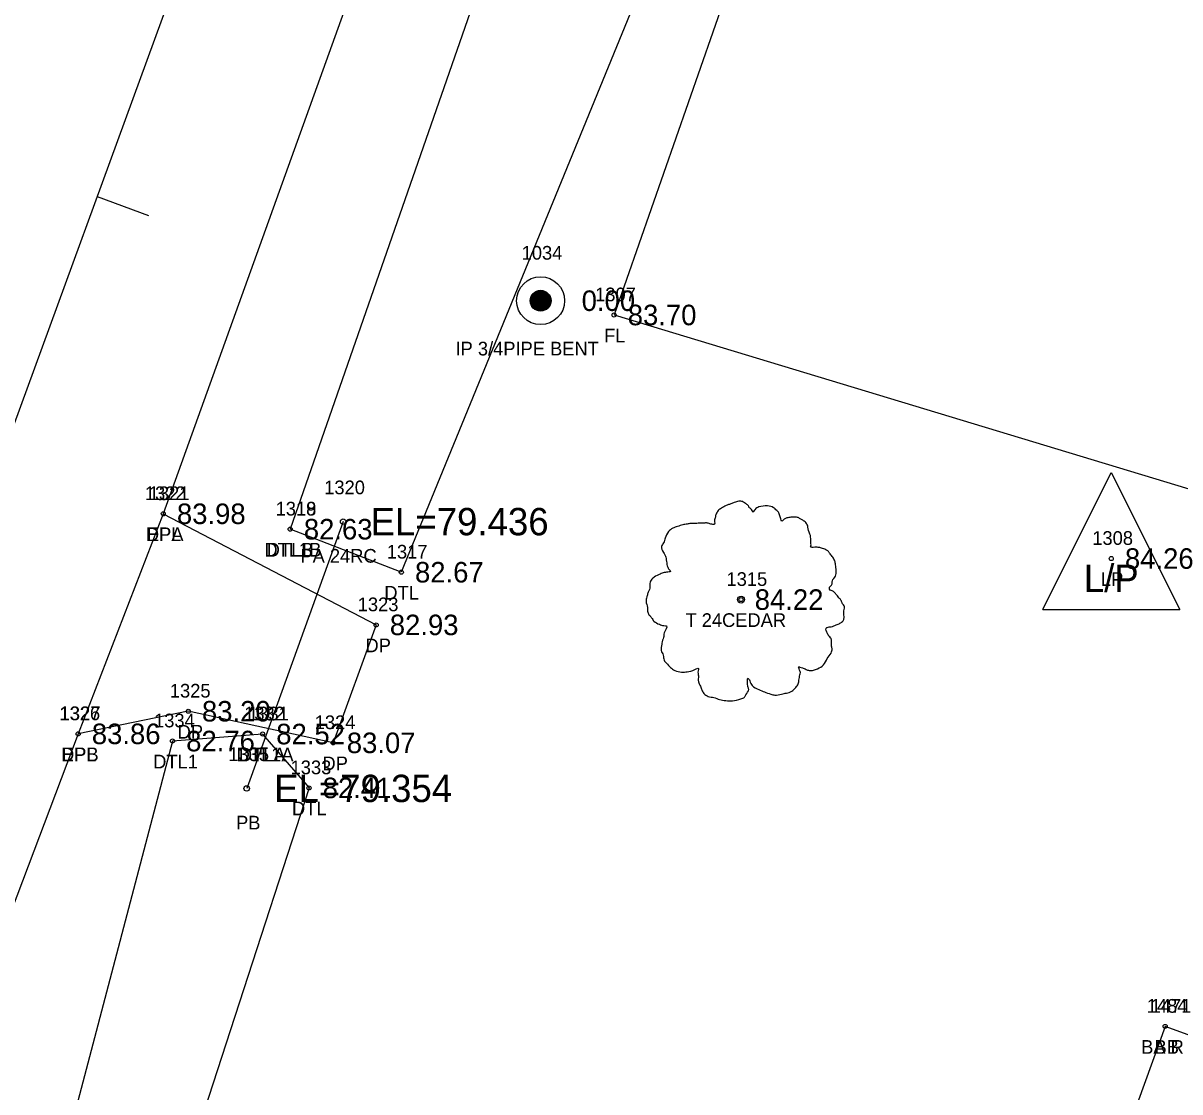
# Model space of a CAD drawing. Extents: x 2139392 to 2143384, y 505395 to 510520.
# Drawn here: x 2141229.8 to 2141314.3, y 509747.3 to 509825.4 of the extents above; entities that cross this region are included whole.
import ezdxf

# ---------------------------------------------------------------- set-up
doc = ezdxf.new("R2010")
doc.units = 0
for name, color, linetype in [('RD_EX_Bldg', 7, 'Continuous'), ('RD_EX_Bldg_txCode', 7, 'Continuous'), ('RD_EX_DR_Pipe', 7, 'Continuous'), ('RD_EX_DR_Pipe_txCode', 7, 'Continuous'), ('RD_EX_Driveway', 7, 'Continuous'), ('RD_EX_Driveway_txCode', 7, 'Continuous'), ('RD_EX_DV_Prop_txCode', 7, 'Continuous'), ('RD_EX_DV_PropPin', 7, 'Continuous'), ('RD_EX_Fence_Other', 7, 'Continuous'), ('RD_EX_Fence_Other_txCode', 7, 'Continuous'), ('RD_EX_H2O', 7, 'Continuous'), ('RD_EX_H2O_txCode', 7, 'Continuous'), ('RD_EX_Road', 7, 'Continuous'), ('RD_EX_Road_txCode', 7, 'Continuous'), ('RD_EX_TX_Driveway_ELEV', 7, 'Continuous'), ('RD_EX_TX_DV_Prop_ELEV', 7, 'Continuous'), ('RD_EX_TX_Fence_Other_ELEV', 7, 'Continuous'), ('RD_EX_TX_H2O_ELEV', 7, 'Continuous'), ('RD_EX_TX_Road_ELEV', 7, 'Continuous'), ('RD_EX_TX_UT_ELEV', 7, 'Continuous'), ('RD_EX_TX_VEG_ELEV', 7, 'Continuous'), ('RD_EX_UT', 7, 'Continuous'), ('RD_EX_UT_txCode', 7, 'Continuous'), ('RD_EX_VEG', 7, 'Continuous'), ('RD_EX_VEG_txCode', 7, 'Continuous'), ('RD_HC_Cl', 7, 'Continuous'), ('RD_HC_Data_Tic', 7, 'Continuous'), ('RD_SMD_Locator', 7, 'Continuous'), ('RD_TX_Pipe_ElevEX', 7, 'Continuous')]:
    doc.layers.add(name, color=color, linetype=linetype)

msp = doc.modelspace()

# ---------------------------------------------------------------- linework, layer by layer
at = {"layer": 'RD_EX_Bldg'}
msp.add_lwpolyline([(2141313.226, 509752.054), (2141304.219, 509727.145), (2141295.277, 509730.38), (2141286.846, 509707.265), (2141295.758, 509703.984), (2141281.839, 509665.488), (2141306.214, 509656.42), (2141337.675, 509743.19), (2141313.226, 509752.054)], dxfattribs=at)
at = {"layer": 'RD_EX_DR_Pipe'}
msp.add_line((2141253.154, 509788.94), (2141246.105, 509769.444), dxfattribs=at)
at = {"layer": 'RD_EX_Driveway'}
msp.add_lwpolyline([(2141240.004, 509789.512), (2141255.562, 509781.393), (2141252.42, 509772.775), (2141241.833, 509775.084), (2141233.785, 509773.43)], dxfattribs=at)
at = {"layer": 'RD_EX_DV_PropPin'}
for p, q in [((2141266.987, 509804.608), (2141266.987, 509805.556)), ((2141267.022, 509804.567), (2141267.022, 509805.597)), ((2141267.057, 509804.531), (2141267.057, 509805.633)), ((2141267.092, 509804.5), (2141267.092, 509805.664)), ((2141267.127, 509804.472), (2141267.127, 509805.692)), ((2141267.162, 509804.447), (2141267.162, 509805.717)), ((2141267.197, 509804.426), (2141267.197, 509805.738)), ((2141267.232, 509804.406), (2141267.232, 509805.758)), ((2141267.267, 509804.389), (2141267.267, 509805.775)), ((2141267.302, 509804.374), (2141267.302, 509805.79)), ((2141267.337, 509804.362), (2141267.337, 509805.802)), ((2141267.372, 509804.351), (2141267.372, 509805.813)), ((2141267.407, 509804.341), (2141267.407, 509805.823)), ((2141267.442, 509804.334), (2141267.442, 509805.83)), ((2141267.477, 509804.328), (2141267.477, 509805.836)), ((2141267.512, 509804.324), (2141267.512, 509805.84)), ((2141267.547, 509804.322), (2141267.547, 509805.842)), ((2141267.582, 509804.321), (2141267.582, 509805.843)), ((2141267.617, 509804.322), (2141267.617, 509805.842)), ((2141267.652, 509804.324), (2141267.652, 509805.84)), ((2141267.687, 509804.328), (2141267.687, 509805.836)), ((2141267.722, 509804.334), (2141267.722, 509805.83)), ((2141267.757, 509804.341), (2141267.757, 509805.823)), ((2141267.792, 509804.351), (2141267.792, 509805.813)), ((2141267.827, 509804.362), (2141267.827, 509805.802)), ((2141267.862, 509804.374), (2141267.862, 509805.79)), ((2141267.897, 509804.389), (2141267.897, 509805.775)), ((2141267.932, 509804.406), (2141267.932, 509805.758)), ((2141267.967, 509804.426), (2141267.967, 509805.738)), ((2141268.002, 509804.447), (2141268.002, 509805.717)), ((2141268.037, 509804.472), (2141268.037, 509805.692)), ((2141268.072, 509804.5), (2141268.072, 509805.664)), ((2141268.107, 509804.531), (2141268.107, 509805.633)), ((2141268.142, 509804.567), (2141268.142, 509805.597)), ((2141268.177, 509804.608), (2141268.177, 509805.556)), ((2141266.846, 509804.886), (2141266.846, 509805.278)), ((2141266.881, 509804.784), (2141266.881, 509805.38)), ((2141266.917, 509804.712), (2141266.917, 509805.452)), ((2141266.952, 509804.655), (2141266.952, 509805.509)), ((2141268.212, 509804.655), (2141268.212, 509805.509)), ((2141268.247, 509804.712), (2141268.247, 509805.452)), ((2141268.282, 509804.784), (2141268.282, 509805.38)), ((2141268.317, 509804.886), (2141268.317, 509805.278))]:
    msp.add_line(p, q, dxfattribs=at)
for radius in [1.75, 0.761]:
    msp.add_circle((2141267.582, 509805.082), radius, dxfattribs=at)
at = {"layer": 'RD_EX_Fence_Other'}
msp.add_lwpolyline([(2141429.607, 510048.099), (2141379.492, 510067.668), (2141363.998, 510064.859), (2141272.951, 509804.039), (2141395.498, 509766.949)], dxfattribs=at)
at = {"layer": 'RD_EX_H2O'}
for points in [[(2141358.836, 510073.731), (2141351.949, 510067.817), (2141335.192, 510023.257), (2141318.106, 509975.216), (2141278.813, 509873.195), (2141249.279, 509788.386)], [(2141358.836, 510073.731), (2141359.889, 510066.727), (2141343.927, 510018.933), (2141329.024, 509971.909), (2141291.465, 509868.396), (2141257.403, 509785.243), (2141249.279, 509788.386)], [(2141247.263, 509773.417), (2141240.68, 509772.906), (2141231.532, 509738.062), (2141231.201, 509735.666), (2141238.226, 509732.828), (2141239.805, 509736.073)], [(2141247.263, 509773.417), (2141250.657, 509769.482), (2141239.805, 509736.073)]]:
    msp.add_lwpolyline(points, dxfattribs=at)
at = {"layer": 'RD_EX_Road'}
msp.add_lwpolyline([(2141412.621, 510288.462), (2141398.288, 510238.157), (2141381.653, 510185.386), (2141379.05, 510176.508), (2141367.082, 510141.573), (2141363.583, 510131.95), (2141345.234, 510080.356), (2141326.054, 510027.028), (2141308.64, 509979.398), (2141271.244, 509876.373), (2141240.004, 509789.512), (2141233.785, 509773.43), (2141223.565, 509746.41), (2141212.184, 509714.932), (2141204.363, 509694.358), (2141197.988, 509676.557), (2141193.665, 509664.596), (2141161.614, 509577.238), (2141123.752, 509473.606), (2141115.502, 509450.651), (2141102.094, 509414.611), (2141086.274, 509371.268), (2141050.416, 509272.831)], dxfattribs=at)
at = {"layer": 'RD_EX_UT'}
for p, q in [((2141304.285, 509782.517), (2141309.285, 509792.517)), ((2141309.285, 509792.517), (2141314.285, 509782.517)), ((2141304.285, 509782.517), (2141314.285, 509782.517))]:
    msp.add_line(p, q, dxfattribs=at)
at = {"layer": 'RD_EX_VEG'}
for centre, radius in [((2141282.23, 509783.242), 0.25), ((2141282.217, 509783.223), 0.0001)]:
    msp.add_circle(centre, radius, dxfattribs=at)
for points in [[(2141282.362, 509790.409), (2141282.062, 509790.434), (2141281.737, 509790.334), (2141281.487, 509790.234), (2141281.262, 509790.159), (2141281.037, 509790.059), (2141280.738, 509789.884), (2141280.513, 509789.684), (2141280.388, 509789.434), (2141280.338, 509789.209), (2141280.288, 509788.935), (2141280.288, 509788.76), (2141280.163, 509788.735), (2141280.013, 509788.76), (2141279.763, 509788.835), (2141279.513, 509788.835), (2141279.263, 509788.835), (2141278.913, 509788.81), (2141278.563, 509788.81), (2141278.289, 509788.76), (2141277.964, 509788.71), (2141277.589, 509788.585), (2141277.239, 509788.46), (2141276.939, 509788.21), (2141276.689, 509787.735), (2141276.564, 509787.385), (2141276.414, 509787.135), (2141276.564, 509786.686), (2141276.739, 509786.336), (2141276.764, 509786.136), (2141276.839, 509785.711), (2141276.939, 509785.486), (2141277.064, 509785.286), (2141276.989, 509785.261), (2141276.614, 509785.211), (2141276.314, 509785.111), (2141275.89, 509784.886), (2141275.665, 509784.661), (2141275.565, 509784.336), (2141275.54, 509783.987), (2141275.44, 509783.787), (2141275.365, 509783.512), (2141275.34, 509783.437), (2141275.29, 509783.112), (2141275.39, 509782.662), (2141275.415, 509782.312), (2141275.54, 509782.087), (2141275.69, 509781.913), (2141275.865, 509781.663), (2141276.264, 509781.438), (2141276.589, 509781.338), (2141276.789, 509781.313), (2141276.614, 509780.813), (2141276.564, 509780.463), (2141276.439, 509780.063), (2141276.439, 509779.988), (2141276.389, 509779.514), (2141276.539, 509779.189), (2141276.614, 509778.814), (2141276.789, 509778.589), (2141277.064, 509778.289), (2141277.389, 509778.064), (2141277.889, 509777.939), (2141278.289, 509777.964), (2141278.863, 509778.139), (2141279.113, 509778.214), (2141279.088, 509778.039), (2141279.113, 509777.664), (2141279.113, 509777.24), (2141279.263, 509776.915), (2141279.363, 509776.64), (2141279.513, 509776.39), (2141279.838, 509776.165), (2141280.238, 509776.09), (2141280.663, 509775.94), (2141281.112, 509775.865), (2141281.612, 509775.84), (2141282.212, 509775.99), (2141282.487, 509776.115), (2141282.587, 509776.29), (2141282.787, 509776.665), (2141282.737, 509776.89), (2141282.762, 509777.49), (2141282.862, 509777.315), (2141283.037, 509776.965), (2141283.536, 509776.665), (2141283.936, 509776.49), (2141284.411, 509776.34), (2141284.711, 509776.265), (2141285.186, 509776.34), (2141285.56, 509776.415), (2141285.935, 509776.54), (2141286.235, 509776.815), (2141286.41, 509777.09), (2141286.46, 509777.365), (2141286.535, 509777.739), (2141286.585, 509777.914)], [(2141286.585, 509777.914), (2141286.51, 509778.089), (2141286.46, 509778.339), (2141286.535, 509778.314), (2141286.71, 509778.264), (2141286.985, 509778.139), (2141287.21, 509778.064), (2141287.535, 509778.089), (2141287.809, 509778.189), (2141288.259, 509778.464), (2141288.534, 509778.939), (2141288.809, 509779.339), (2141288.884, 509779.664), (2141288.834, 509779.888), (2141288.809, 509780.388), (2141288.609, 509780.638), (2141288.559, 509780.763), (2141288.459, 509781.163), (2141288.534, 509781.213), (2141288.809, 509781.263), (2141289.184, 509781.388), (2141289.459, 509781.513), (2141289.684, 509781.688), (2141289.759, 509781.913), (2141289.734, 509782.312), (2141289.784, 509782.712), (2141289.709, 509782.862), (2141289.609, 509783.012), (2141289.534, 509783.212), (2141289.384, 509783.362), (2141289.284, 509783.512), (2141289.184, 509783.612), (2141289.059, 509783.762), (2141288.884, 509783.887), (2141288.734, 509783.937), (2141288.684, 509784.087), (2141288.834, 509784.287), (2141288.884, 509784.386), (2141288.909, 509784.611), (2141289.134, 509784.961), (2141289.184, 509785.361), (2141289.134, 509785.786), (2141289.084, 509786.061), (2141288.934, 509786.336), (2141288.734, 509786.586), (2141288.609, 509786.76), (2141288.434, 509786.885), (2141288.109, 509787.01), (2141287.859, 509787.06), (2141287.51, 509787.06), (2141287.31, 509787.11), (2141287.335, 509787.16), (2141287.335, 509787.31), (2141287.335, 509787.585), (2141287.26, 509788.035), (2141287.11, 509788.535), (2141287.11, 509788.56), (2141287.01, 509788.81), (2141286.785, 509789.009), (2141286.61, 509789.109), (2141286.41, 509789.234), (2141286.16, 509789.259), (2141285.86, 509789.259), (2141285.585, 509789.209), (2141285.385, 509789.109), (2141285.211, 509788.984), (2141285.136, 509789.134), (2141285.036, 509789.434), (2141284.986, 509789.584), (2141284.836, 509789.759), (2141284.611, 509789.959), (2141284.161, 509790.084), (2141283.536, 509790.009), (2141283.236, 509789.809), (2141283.086, 509789.634), (2141283.037, 509789.759), (2141282.837, 509789.959), (2141282.737, 509790.134), (2141282.562, 509790.259), (2141282.412, 509790.359), (2141282.312, 509790.409)]]:
    msp.add_spline(points, degree=3, dxfattribs=at)
at = {"layer": 'RD_HC_Cl'}
msp.add_line((2141333.53, 510081.693), (2140670.514, 508268.365), dxfattribs=at)
at = {"layer": 'RD_HC_Data_Tic'}
msp.add_line((2141235.174, 509812.693), (2141238.931, 509811.32), dxfattribs=at)
at = {"layer": 'RD_SMD_Locator'}
for centre, radius in [((2141267.582, 509805.082), 0.15), ((2141272.951, 509804.039), 0.15), ((2141240.004, 509789.512), 0.15), ((2141240.004, 509789.512), 0.15), ((2141253.154, 509788.94), 0.2), ((2141249.279, 509788.386), 0.15), ((2141249.279, 509788.386), 0.15), ((2141309.285, 509786.241), 0.15), ((2141257.403, 509785.243), 0.15), ((2141282.23, 509783.242), 0.15), ((2141255.562, 509781.393), 0.15), ((2141241.833, 509775.084), 0.15), ((2141233.785, 509773.43), 0.15), ((2141233.785, 509773.43), 0.15), ((2141247.263, 509773.417), 0.15), ((2141247.263, 509773.417), 0.15), ((2141240.68, 509772.906), 0.15), ((2141252.42, 509772.775), 0.15), ((2141246.105, 509769.444), 0.2), ((2141250.657, 509769.482), 0.15), ((2141313.226, 509752.054), 0.15), ((2141313.226, 509752.054), 0.15)]:
    msp.add_circle(centre, radius, dxfattribs=at)

# ---------------------------------------------------------------- texts
at = {"layer": 'RD_EX_Bldg_txCode'}
for s, p in [('1484', (2141311.879, 509753.054)), ('1471', (2141312.163, 509753.054)), ('BA R', (2141311.47, 509750.054)), ('BB', (2141312.446, 509750.054))]:
    msp.add_text(s, height=1, dxfattribs=at).set_placement(p)
at = {"layer": 'RD_EX_DR_Pipe_txCode'}
for s, p in [('1320', (2141251.768, 509790.94)), ('PA 24RC', (2141250.028, 509785.94)), ('1335', (2141244.759, 509771.444)), ('PB', (2141245.325, 509766.444))]:
    msp.add_text(s, height=1, dxfattribs=at).set_placement(p)
at = {"layer": 'RD_EX_Driveway_txCode'}
for s, p in [('1322', (2141238.657, 509790.512)), ('DPA', (2141238.736, 509787.512)), ('1323', (2141254.216, 509782.393)), ('DP', (2141254.783, 509779.393)), ('1325', (2141240.486, 509776.084)), ('1327', (2141232.438, 509774.43)), ('1324', (2141251.074, 509773.775)), ('DP', (2141241.053, 509773.084)), ('DPB', (2141232.533, 509771.43)), ('DP', (2141251.641, 509770.775))]:
    msp.add_text(s, height=1, dxfattribs=at).set_placement(p)
at = {"layer": 'RD_EX_DV_Prop_txCode'}
for s, p in [('1034', (2141266.196, 509808.082)), ('IP 3/4PIPE BENT', (2141261.361, 509801.082))]:
    msp.add_text(s, height=1, dxfattribs=at).set_placement(p)
at = {"layer": 'RD_EX_Fence_Other_txCode'}
for s, p in [('1307', (2141271.565, 509805.039)), ('FL', (2141272.219, 509802.039))]:
    msp.add_text(s, height=1, dxfattribs=at).set_placement(p)
at = {"layer": 'RD_EX_H2O_txCode'}
for s, p in [('1318', (2141248.216, 509789.386)), ('1319', (2141248.216, 509789.386)), ('DTL1B', (2141247.397, 509786.386)), ('DTLB', (2141247.562, 509786.386)), ('1317', (2141256.34, 509786.243)), ('DTL', (2141256.159, 509783.243)), ('1332', (2141245.917, 509774.417)), ('1331', (2141246.2, 509774.417)), ('1334', (2141239.333, 509773.906)), ('DTL1', (2141239.27, 509770.906)), ('DTL1A', (2141245.366, 509771.417)), ('DTLA', (2141245.531, 509771.417)), ('1333', (2141249.311, 509770.482)), ('DTL', (2141249.413, 509767.482))]:
    msp.add_text(s, height=1, dxfattribs=at).set_placement(p)
at = {"layer": 'RD_EX_Road_txCode'}
for s, p in [('1321', (2141238.941, 509790.512)), ('EPL', (2141238.799, 509787.512)), ('1326', (2141232.415, 509774.43)), ('EPL', (2141232.58, 509771.43))]:
    msp.add_text(s, height=1, dxfattribs=at).set_placement(p)
at = {"layer": 'RD_EX_TX_Driveway_ELEV'}
for s, p in [('83.98', (2141241.004, 509788.762)), ('82.93', (2141256.562, 509780.643)), ('83.20', (2141242.833, 509774.334)), ('83.86', (2141234.785, 509772.68)), ('83.07', (2141253.42, 509772.025))]:
    msp.add_text(s, height=1.5, dxfattribs=at).set_placement(p)
at = {"layer": 'RD_EX_TX_DV_Prop_ELEV'}
msp.add_text('0.00', height=1.5, dxfattribs=at).set_placement((2141270.582, 509804.332))
at = {"layer": 'RD_EX_TX_Fence_Other_ELEV'}
msp.add_text('83.70', height=1.5, dxfattribs=at).set_placement((2141273.951, 509803.289))
at = {"layer": 'RD_EX_TX_H2O_ELEV'}
for s, p in [('82.63', (2141250.279, 509787.636)), ('82.63', (2141250.279, 509787.636)), ('82.67', (2141258.403, 509784.493)), ('82.76', (2141241.68, 509772.156)), ('82.52', (2141248.263, 509772.667)), ('82.52', (2141248.263, 509772.667)), ('82.41', (2141251.657, 509768.732))]:
    msp.add_text(s, height=1.5, dxfattribs=at).set_placement(p)
at = {"layer": 'RD_EX_TX_Road_ELEV'}
for s, p in [('83.98', (2141241.004, 509788.762)), ('83.86', (2141234.785, 509772.68))]:
    msp.add_text(s, height=1.5, dxfattribs=at).set_placement(p)
at = {"layer": 'RD_EX_TX_UT_ELEV'}
msp.add_text('84.26', height=1.5, dxfattribs=at).set_placement((2141310.285, 509785.491))
at = {"layer": 'RD_EX_TX_VEG_ELEV'}
msp.add_text('84.22', height=1.5, dxfattribs=at).set_placement((2141283.23, 509782.492))
at = {"layer": 'RD_EX_UT'}
msp.add_text('L/P', height=2, dxfattribs=at).set_placement((2141307.276, 509783.798))
at = {"layer": 'RD_EX_UT_txCode'}
for s, p in [('1308', (2141307.899, 509787.241)), ('LP', (2141308.529, 509784.241))]:
    msp.add_text(s, height=1, dxfattribs=at).set_placement(p)
at = {"layer": 'RD_EX_VEG_txCode'}
for s, p in [('1315', (2141281.167, 509784.242)), ('T 24CEDAR', (2141278.167, 509781.242))]:
    msp.add_text(s, height=1, dxfattribs=at).set_placement(p)
at = {"layer": 'RD_TX_Pipe_ElevEX'}
for s, p in [('EL=79.436', (2141255.154, 509787.94)), ('EL=79.354', (2141248.105, 509768.444))]:
    msp.add_text(s, height=2, dxfattribs=at).set_placement(p)

doc.saveas('drawing.dxf')
